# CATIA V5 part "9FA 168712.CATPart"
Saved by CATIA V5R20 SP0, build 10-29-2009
Part number: 9FA 168712
Revision: ANY
Definition: UNKNOWN
Nomenclature: 9FA 168712
Source: Unknown
Bounding box of the stored display mesh (mm): x -8 to 8, y 0.13 to 20.13, z -8 to 8
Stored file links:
  C:\Users\Utente\Desktop\IO LAVORO\3D X SITO CF\CUMSA\3D files FA\FA 1687SF\9FA 168712.CATPart

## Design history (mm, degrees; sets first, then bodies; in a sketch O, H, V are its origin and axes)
Body1 "Cortar-Extruir4" (main body)
  Solid1: solid without history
